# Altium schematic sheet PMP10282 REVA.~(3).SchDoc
size 431 x 279 mm; Date: Not shown in title block; ApprovedBy: Not shown in title block; CheckedBy: Not shown in title block; Author: Not shown in title block; CompanyName: Not shown in title block; Engineer: Not shown in title block; Organization: Not shown in title block; Address1: Not shown in title block; Address2: Not shown in title block; Address3: Not shown in title block; Address4: Not shown in title block; DocumentNumber: 1; Revision: Use project parameter SCH_Rev; SheetNumber: 1; SheetTotal: 1; PageSetup: Record=PageOptions|CenterHorizontal=True|CenterVertical=True|PrintScale=1.00|XCorrection=1.00|YCorrection=1.00|PrintKind=0|BorderSize=5000000|LeftOffset=0|BottomOffset=0|Orientation=2|PaperLength=1000|PaperWidth=1000|Scale=100|PaperSource=15|PrintQuality=600|MediaType=1|DitherType=10|PaperKind=Letter|PrintScaleMode=1
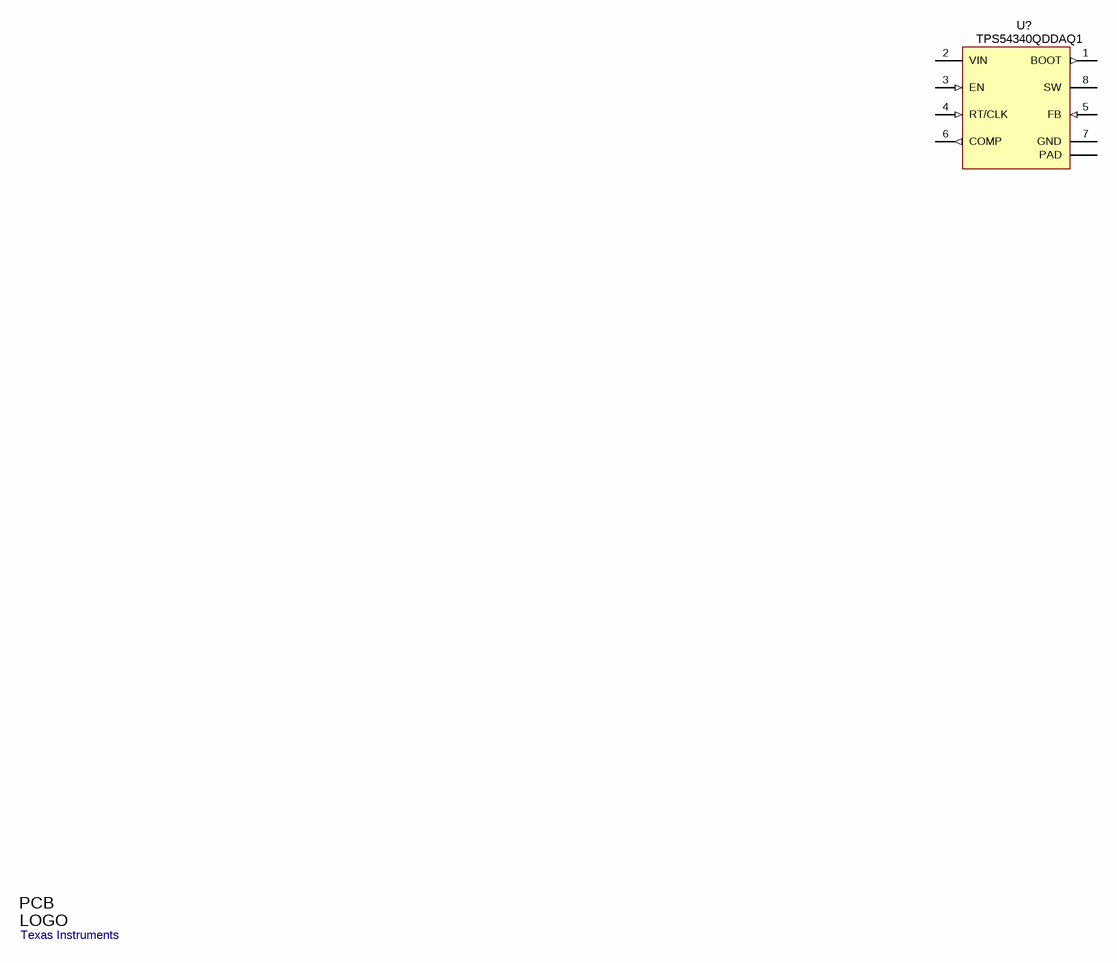
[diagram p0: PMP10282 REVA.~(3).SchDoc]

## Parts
Logo1  Texas Instruments  [TI_Stacked_Overlay_Small]  (no BOM)
U?  TPS54340QDDAQ1  [DDA0008E_N]

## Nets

Not connected (* = marked no-connect by the designer): U? 1(BOOT) 2(VIN) 3(EN) 4(RT/CLK) 5(FB) 6(COMP) 7(GND) 8(SW) 9(PAD)

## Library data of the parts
Logo1 = TI_Logo: Texas Instrument Corporate Signature; SymbolCreator: a0412235
U? = TPS54340DDA: 42 V Input, 3.5 A, Step Down DC-DC Converter with Eco-mode, DDA0008E; Alternate Manufacturer: None; Manufacturer: Texas Instruments; SymbolCreator: a0411947; CompType: IC; U/M: EA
